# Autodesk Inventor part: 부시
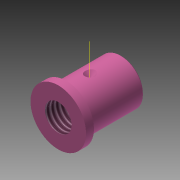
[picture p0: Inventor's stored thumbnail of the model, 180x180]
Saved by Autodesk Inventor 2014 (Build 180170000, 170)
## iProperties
Created: 2019-04
Part Number: 부시
Material: 강철, 연강
Document SubType Name: Modeling
Designer: mduedu
Density: 1 g/cm^3
Appearance: Pink
Author: mduedu
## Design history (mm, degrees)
sketch "스케치1"
  geometry: L1 (0, 0)-(3, 0); L2 (3, 0)-(3, 10.5); L3 (3, 10.5)-(0, 10.5); L4 (0, 10.5)-(0, 0); L5 (3, 0)-(24, 0); L6 (24, 0)-(24, 8.5); L7 (24, 8.5)-(3, 8.5); L8 (3, 8.5)-(3, 0)
  constraints: 16 end point, 4 parallel, 2 horizontal, 2 perpendicular
  dimensions: "d0" = 3 distance of L2.end L3.end; "d2" = 24 distance between parallel lines of L6 L4; "d3" = 17 diameter of L7 L5; "d4" = 21 diameter of L3 L1
revolve "회전1" sketch "스케치1" stored, may be unused: angle "d5" = 90 deg
sketch "스케치2"
  geometry: L1 (3, 8.5)-(24, 8.5) reference; L2 (12, 8.5)-(12, 6.5); L3 (12, 6.5)-(14, 8.5); L4 (0, -10.5)-(0, 10.5) reference; 1 further point
  constraints: 4 end point, 2 point on line, 1 perpendicular
  dimensions: "d6" = 12 distance from line of L2.start L4; "d7" = 2 distance of L2.start L3.end; "d8" = 45 deg angle of L3 L2
revolve "회전2" sketch "스케치2" stored, may be unused: angle "d9" = 90 deg
hole "구멍1" diameter "d12" = 10.106; stored, may be unused: countersink angle "d16" = 90 deg, drill point angle "d18" = 118 deg; dims "d10" = 10, "d11" = 10, "d13" = 39, "d14" = 4, "d15" = 2, "d17" = 8
chamfer "모따기1" distance "d19" = 0.5; stored, may be unused: second distance "d20" = 2, angle "d21" = 45 deg
node "작업점1"
  node "작업 평면1"
  node "작업축1"
workaxis "Work Axis2"
node "솔리드1"
